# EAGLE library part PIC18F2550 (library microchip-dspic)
PIC18F Flash Microcontroller with USB port
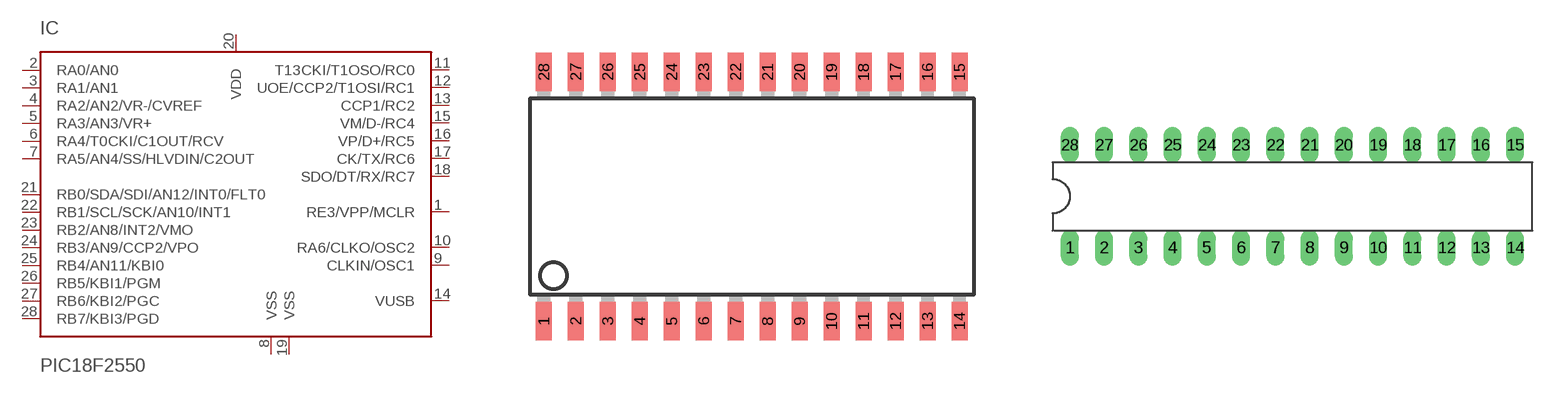
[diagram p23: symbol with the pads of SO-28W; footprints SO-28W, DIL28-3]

Designator prefix IC

## PIC18F2550SO  [SO-28W]
1  RE3/VPP/MCLR
2  RA0/AN0
3  RA1/AN1
4  RA2/AN2/VR-/CVREF
5  RA3/AN3/VR+
6  RA4/T0CKI/C1OUT/RCV
7  RA5/AN4/SS/HLVDIN/C2OUT
8  VSS  pwr
9  CLKIN/OSC1  in
10  RA6/CLKO/OSC2
11  T13CKI/T1OSO/RC0
12  UOE/CCP2/T1OSI/RC1
13  CCP1/RC2
14  VUSB  pwr
15  VM/D-/RC4
16  VP/D+/RC5
17  CK/TX/RC6
18  SDO/DT/RX/RC7
19  VSS  pwr
20  VDD  pwr
21  RB0/SDA/SDI/AN12/INT0/FLT0
22  RB1/SCL/SCK/AN10/INT1
23  RB2/AN8/INT2/VMO
24  RB3/AN9/CCP2/VPO
25  RB4/AN11/KBI0
26  RB5/KBI1/PGM
27  RB6/KBI2/PGC
28  RB7/KBI3/PGD

## PIC18F2550SP  [DIL28-3]
Pads as for SO-28W

## Footprint SO-28W (pad centres in mm)
Small Outline Wide Plastic Gull Wing 300-mil body, package type SO
smd 0.635 x 1.524: 1 -7.62,-4.953; 2 -6.35,-4.953; 3 -5.08,-4.953; 4 -3.81,-4.953; 5 -2.54,-4.953; 6 -1.27,-4.953; 7 0,-4.953; 8 1.27,-4.953; 9 2.54,-4.953; 10 3.81,-4.953; 11 5.08,-4.953; 12 6.35,-4.953; 13 7.62,-4.953; 14 8.89,-4.953; 15 8.89,4.953; 16 7.62,4.953; 17 6.35,4.953; 18 5.08,4.953; 19 3.81,4.953; 20 2.54,4.953; 21 1.27,4.953; 22 0,4.953; 23 -1.27,4.953; 24 -2.54,4.953; 25 -3.81,4.953; 26 -5.08,4.953; 27 -6.35,4.953; 28 -7.62,4.953

## Footprint DIL28-3 (pad centres in mm)
Dual In Line package type P
drill 0.813 long: 1 -16.51,-3.81; 2 -13.97,-3.81; 3 -11.43,-3.81; 4 -8.89,-3.81; 5 -6.35,-3.81; 6 -3.81,-3.81; 7 -1.27,-3.81; 8 1.27,-3.81; 9 3.81,-3.81; 10 6.35,-3.81; 11 8.89,-3.81; 12 11.43,-3.81; 13 13.97,-3.81; 14 16.51,-3.81; 15 16.51,3.81; 16 13.97,3.81; 17 11.43,3.81; 18 8.89,3.81; 19 6.35,3.81; 20 3.81,3.81; 21 1.27,3.81; 22 -1.27,3.81; 23 -3.81,3.81; 24 -6.35,3.81; 25 -8.89,3.81; 26 -11.43,3.81; 27 -13.97,3.81; 28 -16.51,3.81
